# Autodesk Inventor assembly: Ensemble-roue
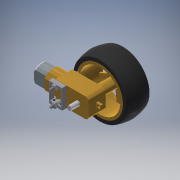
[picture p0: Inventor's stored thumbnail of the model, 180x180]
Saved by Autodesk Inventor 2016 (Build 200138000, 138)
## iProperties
Created: 2018-03
Part Number: Ensemble-roue
Material: Générique
Document SubType Name: Assembly
Designer: Bruno
Author: Bruno
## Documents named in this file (3)
- D:\Cours\1-Cours-2017-18\2SI\projet\Inventor\Ensemble-roue.iam
- D:\Cours\1-Cours-2017-18\2SI\projet\Inventor\Motoreducteur.iam
- D:\Cours\1-Cours-2017-18\2SI\projet\Inventor\Roue.iam
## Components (2 placed, 2 different names)
1. Motoreducteur:1 [sub-assembly] — Placage:1, Placage:2
2. Roue:1 [sub-assembly] — Placage:1, Placage:2
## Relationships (2: Mate 2)
- Placage:1 [Mate]: Motoreducteur:1 ↔ Roue:1
- Placage:2 [Mate]: Motoreducteur:1 ↔ Roue:1
